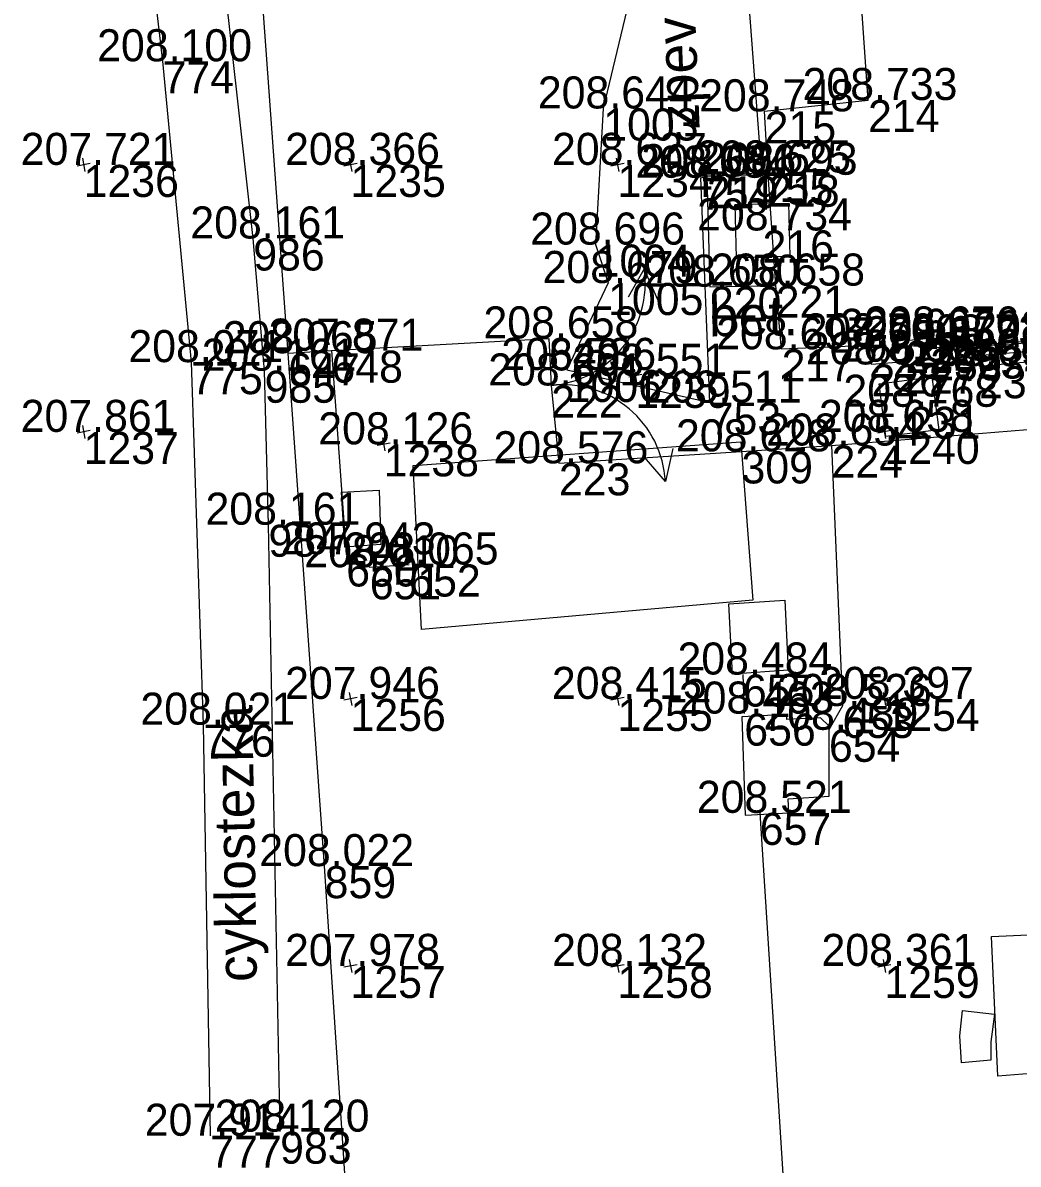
# Model space of a CAD drawing. Extents: x -556590 to -554855, y -1137918 to -1135717.
# Drawn here: x -554982.28 to -554944.99, y -1137757.42 to -1137714.68 of the extents above; entities that cross this region are included whole.
import ezdxf

# ---------------------------------------------------------------- set-up
doc = ezdxf.new("R2010")
doc.units = 0
for name, color, linetype in [('Vrstva 16', 7, 'Continuous'), ('Vrstva 17', 7, 'Continuous'), ('Vrstva 23', 7, 'Continuous'), ('Vrstva 41', 7, 'Continuous'), ('Vrstva 47', 7, 'Continuous'), ('Vrstva 49', 7, 'Continuous'), ('Vrstva 51', 7, 'Continuous'), ('Vrstva 60', 7, 'Continuous'), ('Vrstva 61', 7, 'Continuous')]:
    doc.layers.add(name, color=color, linetype=linetype)

msp = doc.modelspace()

# ---------------------------------------------------------------- linework, layer by layer
at = {"layer": 'Vrstva 16'}
msp.add_lwpolyline([(-554954.353, -1137720.369), (-554956.652, -1137720.423), (-554956.537, -1137724.561), (-554954.072, -1137724.52), (-554954.353, -1137720.369)], dxfattribs=at)
at = {"layer": 'Vrstva 17'}
for p, q in [((-554951.98, -1137730.511), (-554937.843, -1137729.353)), ((-554955.354, -1137730.73), (-554951.98, -1137730.511)), ((-554955.3, -1137739.087), (-554955.249, -1137740.55)), ((-554954.67, -1137744.267), (-554953.509, -1137762.307))]:
    msp.add_line(p, q, dxfattribs=at)
for points in [[(-554953.509, -1137762.307), (-554969.868, -1137763.056), (-554970.971, -1137746.263), (-554972.332, -1137727.052), (-554973.806, -1137706.758), (-554973.974, -1137703.936), (-554973.997, -1137703.261)], [(-554958.483, -1137725.048), (-554959, -1137723.893), (-554959.597, -1137724.958)], [(-554972.332, -1137727.052), (-554970.716, -1137726.957), (-554962.566, -1137726.499)], [(-554962.566, -1137726.499), (-554962.483, -1137728.261), (-554962.192, -1137731.175)], [(-554970.716, -1137726.957), (-554970.161, -1137734.59), (-554969.281, -1137735.07), (-554967.799, -1137734.966)], [(-554957.926, -1137730.62), (-554958.205, -1137731.854), (-554959.001, -1137730.928)], [(-554951.98, -1137730.511), (-554951.571, -1137740.263), (-554952.078, -1137741.156)]]:
    msp.add_lwpolyline(points, dxfattribs=at)
for centre, start, end in [((-554962.795, -1137724.439), 274.6681, 8.188), ((-554962.033, -1137732.069), 3.2176, 96.7375)]:
    msp.add_arc(centre, 3.834, start, end, dxfattribs=at)
at = {"layer": 'Vrstva 23'}
for p, q in [((-554944.283, -1137726.965), (-554946.502, -1137727.152)), ((-554962.192, -1137731.175), (-554955.354, -1137730.73))]:
    msp.add_line(p, q, dxfattribs=at)
for points in [[(-554936.962, -1137725.77), (-554937.612, -1137725.918), (-554942.449, -1137726.25), (-554942.593, -1137726.475), (-554948.283, -1137726.866), (-554948.301, -1137726.503), (-554949.214, -1137726.588), (-554949.216, -1137727.371), (-554950.485, -1137727.473), (-554950.573, -1137726.763), (-554953.849, -1137726.906), (-554954.072, -1137724.52), (-554954.353, -1137720.369), (-554954.486, -1137717.994), (-554950.612, -1137717.57), (-554951.566, -1137703.736)], [(-554946.547, -1137726.803), (-554946.453, -1137727.539), (-554944.242, -1137727.335), (-554944.317, -1137726.654), (-554946.547, -1137726.803)], [(-554955.379, -1137730.366), (-554954.924, -1137736.305), (-554967.337, -1137737.396), (-554967.649, -1137731.255), (-554955.379, -1137730.366)], [(-554968.931, -1137732.178), (-554968.859, -1137734.219), (-554970.215, -1137734.32), (-554970.334, -1137732.256), (-554968.931, -1137732.178)], [(-554953.731, -1137736.305), (-554953.6, -1137738.924), (-554955.689, -1137739.067), (-554955.826, -1137736.435), (-554953.731, -1137736.305)], [(-554955.341, -1137740.666), (-554955.219, -1137744.358), (-554953.583, -1137744.27), (-554953.599, -1137743.744), (-554952.074, -1137743.637), (-554952.064, -1137741.024), (-554952.394, -1137740.711), (-554953.656, -1137740.771), (-554953.662, -1137740.58), (-554955.341, -1137740.666)], [(-554943.227, -1137748.774), (-554942.94, -1137753.906), (-554945.746, -1137754.124), (-554945.984, -1137748.892), (-554943.227, -1137748.774)], [(-554945.871, -1137751.807), (-554946.013, -1137752.846), (-554946.014, -1137753.532), (-554947.106, -1137753.627), (-554947.169, -1137752.618), (-554947.078, -1137751.671), (-554945.871, -1137751.807)]]:
    msp.add_lwpolyline(points, dxfattribs=at)
at = {"layer": 'Vrstva 41'}
msp.add_lwpolyline([(-554950.201, -1137728.194), (-554948.217, -1137727.94), (-554947.963, -1137729.924), (-554949.947, -1137730.178), (-554950.201, -1137728.194)], dxfattribs=at)
at = {"layer": 'Vrstva 47'}
msp.add_lwpolyline([(-554953.538, -1137723.428), (-554955.537, -1137723.483), (-554955.592, -1137721.484), (-554953.593, -1137721.429), (-554953.538, -1137723.428)], dxfattribs=at)
at = {"layer": 'Vrstva 49'}
for p, q in [((-554979.754, -1137719.953), (-554980.246, -1137720.047)), ((-554980.047, -1137719.754), (-554979.953, -1137720.246)), ((-554969.754, -1137719.953), (-554970.246, -1137720.047)), ((-554970.047, -1137719.754), (-554969.953, -1137720.246)), ((-554959.754, -1137719.953), (-554960.246, -1137720.047)), ((-554960.047, -1137719.754), (-554959.953, -1137720.246)), ((-554959.378, -1137727.655), (-554959.284, -1137728.147)), ((-554959.085, -1137727.854), (-554959.577, -1137727.948)), ((-554979.754, -1137729.953), (-554980.246, -1137730.047)), ((-554980.047, -1137729.754), (-554979.953, -1137730.246)), ((-554949.754, -1137729.953), (-554950.246, -1137730.047)), ((-554950.047, -1137729.754), (-554949.953, -1137730.246)), ((-554968.803, -1137730.22), (-554968.709, -1137730.712)), ((-554968.51, -1137730.419), (-554969.002, -1137730.513)), ((-554970.047, -1137739.754), (-554969.953, -1137740.246)), ((-554960.047, -1137739.754), (-554959.953, -1137740.246)), ((-554950.047, -1137739.754), (-554949.953, -1137740.246)), ((-554969.754, -1137739.953), (-554970.246, -1137740.047)), ((-554959.754, -1137739.953), (-554960.246, -1137740.047)), ((-554949.754, -1137739.953), (-554950.246, -1137740.047)), ((-554969.754, -1137749.953), (-554970.246, -1137750.047)), ((-554970.047, -1137749.754), (-554969.953, -1137750.246)), ((-554959.754, -1137749.953), (-554960.246, -1137750.047)), ((-554960.047, -1137749.754), (-554959.953, -1137750.246)), ((-554949.754, -1137749.953), (-554950.246, -1137750.047)), ((-554950.047, -1137749.754), (-554949.953, -1137750.246))]:
    msp.add_line(p, q, dxfattribs=at)
at = {"layer": 'Vrstva 51'}
for points in [[(-554969.785, -1137628.147), (-554967.399, -1137653.447), (-554966.769, -1137664.877), (-554966.888, -1137675.364), (-554967.838, -1137681.325), (-554969.426, -1137687.024), (-554971.39, -1137690.685), (-554975.343, -1137695.897), (-554977.115, -1137698.646), (-554978.514, -1137693.064), (-554980.357, -1137693.689), (-554978.168, -1137701.789), (-554978.169, -1137706.508), (-554977.04, -1137716.12), (-554975.965, -1137727.387), (-554975.515, -1137740.965), (-554975.257, -1137756.361)], [(-554972.638, -1137756.206), (-554973.075, -1137733.475), (-554973.218, -1137727.708), (-554973.644, -1137722.756), (-554975.49, -1137706.199), (-554975.665, -1137703.469), (-554975.108, -1137700.795), (-554973.317, -1137697.546), (-554969.739, -1137692.478), (-554967.391, -1137688.754), (-554966.215, -1137686.165), (-554964.966, -1137680.854), (-554963.935, -1137674.375), (-554963.882, -1137667.989), (-554964.172, -1137662.776), (-554962.839, -1137664.18)], [(-554959.937, -1137681.133), (-554958.62, -1137696.847), (-554958.628, -1137709.906), (-554960.531, -1137717.887), (-554960.817, -1137722.985), (-554960.351, -1137724.423), (-554961.9, -1137727.679)], [(-554961.9, -1137727.679), (-554956.544, -1137728.902), (-554956.873, -1137720.481), (-554956.652, -1137720.423), (-554954.594, -1137720.285), (-554955.148, -1137712.82), (-554952.02, -1137712.38), (-554952.407, -1137709.32), (-554955.389, -1137709.42), (-554955.865, -1137703.797), (-554955.543, -1137697.151), (-554955.755, -1137693.952), (-554956.919, -1137684.337)]]:
    msp.add_lwpolyline(points, dxfattribs=at)
at = {"layer": 'Vrstva 60'}
for p, q in [((-554977.04, -1137716.12), (-554977.04, -1137716.12)), ((-554950.612, -1137717.57), (-554950.612, -1137717.57)), ((-554960.531, -1137717.887), (-554960.531, -1137717.887)), ((-554954.486, -1137717.994), (-554954.486, -1137717.994)), ((-554980, -1137720), (-554980, -1137720)), ((-554970, -1137720), (-554970, -1137720)), ((-554960, -1137720), (-554960, -1137720)), ((-554956.873, -1137720.481), (-554956.873, -1137720.481)), ((-554956.652, -1137720.423), (-554956.652, -1137720.423)), ((-554954.594, -1137720.285), (-554954.594, -1137720.285)), ((-554954.353, -1137720.369), (-554954.353, -1137720.369)), ((-554954.565, -1137722.456), (-554954.565, -1137722.456)), ((-554973.644, -1137722.756), (-554973.644, -1137722.756)), ((-554960.817, -1137722.985), (-554960.817, -1137722.985)), ((-554960.351, -1137724.423), (-554960.351, -1137724.423)), ((-554956.537, -1137724.561), (-554956.537, -1137724.561)), ((-554954.072, -1137724.52), (-554954.072, -1137724.52)), ((-554962.566, -1137726.499), (-554962.566, -1137726.499)), ((-554948.301, -1137726.503), (-554948.301, -1137726.503)), ((-554970.716, -1137726.957), (-554970.716, -1137726.957)), ((-554953.849, -1137726.906), (-554953.849, -1137726.906)), ((-554950.573, -1137726.763), (-554950.573, -1137726.763)), ((-554949.214, -1137726.588), (-554949.214, -1137726.588)), ((-554948.283, -1137726.866), (-554948.283, -1137726.866)), ((-554946.547, -1137726.803), (-554946.547, -1137726.803)), ((-554975.965, -1137727.387), (-554975.965, -1137727.387)), ((-554972.332, -1137727.052), (-554972.332, -1137727.052)), ((-554949.216, -1137727.371), (-554949.216, -1137727.371)), ((-554973.218, -1137727.708), (-554973.218, -1137727.708)), ((-554961.9, -1137727.679), (-554961.9, -1137727.679)), ((-554950.485, -1137727.473), (-554950.485, -1137727.473)), ((-554946.453, -1137727.539), (-554946.453, -1137727.539)), ((-554962.483, -1137728.261), (-554962.483, -1137728.261)), ((-554959.331, -1137727.901), (-554959.331, -1137727.901)), ((-554956.544, -1137728.902), (-554956.544, -1137728.902)), ((-554949.082, -1137729.059), (-554949.082, -1137729.059)), ((-554980, -1137730), (-554980, -1137730)), ((-554950, -1137730), (-554950, -1137730)), ((-554968.756, -1137730.466), (-554968.756, -1137730.466)), ((-554955.354, -1137730.73), (-554955.354, -1137730.73)), ((-554951.98, -1137730.511), (-554951.98, -1137730.511)), ((-554962.192, -1137731.175), (-554962.192, -1137731.175)), ((-554973.075, -1137733.475), (-554973.075, -1137733.475)), ((-554970.161, -1137734.59), (-554970.161, -1137734.59)), ((-554969.281, -1137735.07), (-554969.281, -1137735.07)), ((-554967.799, -1137734.966), (-554967.799, -1137734.966)), ((-554955.3, -1137739.087), (-554955.3, -1137739.087)), ((-554970, -1137740), (-554970, -1137740)), ((-554960, -1137740), (-554960, -1137740)), ((-554950, -1137740), (-554950, -1137740)), ((-554955.249, -1137740.55), (-554955.249, -1137740.55)), ((-554951.571, -1137740.263), (-554951.571, -1137740.263)), ((-554975.515, -1137740.965), (-554975.515, -1137740.965)), ((-554952.078, -1137741.156), (-554952.078, -1137741.156)), ((-554954.67, -1137744.267), (-554954.67, -1137744.267)), ((-554970.971, -1137746.263), (-554970.971, -1137746.263)), ((-554970, -1137750), (-554970, -1137750)), ((-554960, -1137750), (-554960, -1137750)), ((-554950, -1137750), (-554950, -1137750)), ((-554975.257, -1137756.361), (-554975.257, -1137756.361)), ((-554972.638, -1137756.206), (-554972.638, -1137756.206))]:
    msp.add_line(p, q, dxfattribs=at)

# ---------------------------------------------------------------- texts
at = {"layer": 'Vrstva 16'}
msp.add_text('bet.', height=1.5, rotation=0.9529, dxfattribs=at).set_placement((-554956.567, -1137726.43))
at = {"layer": 'Vrstva 51'}
for s, rotation, p in [('zpevn.', 92.2374, (-554956.919, -1137718.672)), ('cyklostezka', 90.96, (-554973.506, -1137750.592))]:
    msp.add_text(s, height=1.5, rotation=rotation, dxfattribs=at).set_placement(p)
at = {"layer": 'Vrstva 60'}
for s, p in [('774', (-554977.04, -1137717.32)), ('214', (-554950.612, -1137718.77)), ('1003', (-554960.531, -1137719.087)), ('215', (-554954.486, -1137719.194)), ('1236', (-554980, -1137721.2)), ('1235', (-554970, -1137721.2)), ('1234', (-554960, -1137721.2)), ('754', (-554956.873, -1137721.681)), ('219', (-554956.652, -1137721.623)), ('755', (-554954.594, -1137721.485)), ('218', (-554954.353, -1137721.569)), ('216', (-554954.565, -1137723.656)), ('986', (-554973.644, -1137723.956)), ('1004', (-554960.817, -1137724.185)), ('1005', (-554960.351, -1137725.623)), ('220', (-554956.537, -1137725.761)), ('221', (-554954.072, -1137725.72)), ('649', (-554962.566, -1137727.699)), ('229', (-554948.301, -1137727.703)), ('648', (-554970.716, -1137728.157)), ('217', (-554953.849, -1137728.106)), ('225', (-554950.573, -1137727.963)), ('228', (-554949.214, -1137727.788)), ('230', (-554948.283, -1137728.066)), ('234', (-554946.547, -1137728.003)), ('775', (-554975.965, -1137728.587)), ('647', (-554972.332, -1137728.252)), ('227', (-554949.216, -1137728.571)), ('985', (-554973.218, -1137728.908)), ('1006', (-554961.9, -1137728.879)), ('226', (-554950.485, -1137728.673)), ('235', (-554946.453, -1137728.739)), ('222', (-554962.483, -1137729.461)), ('1239', (-554959.331, -1137729.101)), ('753', (-554956.544, -1137730.102)), ('231', (-554949.082, -1137730.259)), ('1237', (-554980, -1137731.2)), ('1240', (-554950, -1137731.2)), ('1238', (-554968.756, -1137731.666)), ('309', (-554955.354, -1137731.93)), ('224', (-554951.98, -1137731.711)), ('223', (-554962.192, -1137732.375)), ('984', (-554973.075, -1137734.675)), ('650', (-554970.161, -1137735.79)), ('651', (-554969.281, -1137736.27)), ('652', (-554967.799, -1137736.166)), ('655', (-554955.3, -1137740.287)), ('1256', (-554970, -1137741.2)), ('1255', (-554960, -1137741.2)), ('653', (-554951.571, -1137741.463)), ('1254', (-554950, -1137741.2)), ('656', (-554955.249, -1137741.75)), ('776', (-554975.515, -1137742.165)), ('654', (-554952.078, -1137742.356)), ('657', (-554954.67, -1137745.467)), ('859', (-554970.971, -1137747.463)), ('1257', (-554970, -1137751.2)), ('1258', (-554960, -1137751.2)), ('1259', (-554950, -1137751.2)), ('777', (-554975.257, -1137757.561)), ('983', (-554972.638, -1137757.406))]:
    msp.add_text(s, height=1.2, dxfattribs=at).set_placement(p)
at = {"layer": 'Vrstva 61'}
for s, p in [('208.100', (-554979.491, -1137716.12)), ('208.644', (-554962.982, -1137717.887)), ('208.733', (-554953.064, -1137717.57)), ('208.748', (-554956.94, -1137717.994)), ('207.721', (-554982.357, -1137720)), ('208.366', (-554972.452, -1137720)), ('208.627', (-554962.452, -1137720)), ('208.684', (-554959.324, -1137720.481)), ('208.696', (-554959.104, -1137720.423)), ('208.625', (-554957.05, -1137720.285)), ('208.693', (-554956.805, -1137720.369)), ('208.734', (-554957.016, -1137722.456)), ('208.161', (-554976.001, -1137722.756)), ('208.696', (-554963.269, -1137722.985)), ('208.679', (-554962.805, -1137724.423)), ('208.650', (-554958.988, -1137724.561)), ('208.658', (-554956.526, -1137724.52)), ('208.658', (-554965.02, -1137726.499)), ('208.697', (-554956.301, -1137726.906)), ('208.704', (-554953.024, -1137726.763)), ('208.697', (-554951.666, -1137726.588)), ('208.676', (-554950.753, -1137726.503)), ('208.659', (-554950.737, -1137726.866)), ('208.737', (-554948.999, -1137726.803)), ('208.921', (-554946.674, -1137726.654)), ('208.065', (-554974.788, -1137727.052)), ('207.871', (-554973.073, -1137726.957)), ('208.809', (-554946.696, -1137727.335)), ('208.071', (-554978.322, -1137727.387)), ('208.161', (-554975.575, -1137727.708)), ('208.536', (-554964.352, -1137727.679)), ('208.678', (-554952.939, -1137727.473)), ('208.688', (-554951.67, -1137727.371)), ('208.696', (-554948.905, -1137727.539)), ('208.551', (-554961.688, -1137727.901)), ('208.601', (-554964.84, -1137728.261)), ('208.511', (-554958.901, -1137728.902)), ('208.768', (-554951.536, -1137729.059)), ('207.861', (-554982.357, -1137730)), ('208.658', (-554952.454, -1137730)), ('208.126', (-554971.208, -1137730.466)), ('208.628', (-554957.808, -1137730.73)), ('208.654', (-554954.431, -1137730.511)), ('208.576', (-554964.644, -1137731.175)), ('208.161', (-554975.432, -1137733.475)), ('207.943', (-554972.613, -1137734.59)), ('208.065', (-554970.255, -1137734.966)), ('208.010', (-554971.732, -1137735.07)), ('208.484', (-554957.751, -1137739.087)), ('207.946', (-554972.452, -1137740)), ('208.415', (-554962.456, -1137740)), ('208.397', (-554952.452, -1137740)), ('208.463', (-554957.701, -1137740.55)), ('208.526', (-554954.023, -1137740.263)), ('208.021', (-554977.872, -1137740.965)), ('208.489', (-554954.532, -1137741.156)), ('208.521', (-554957.027, -1137744.267)), ('208.022', (-554973.419, -1137746.263)), ('207.978', (-554972.454, -1137750)), ('208.132', (-554962.448, -1137750)), ('208.361', (-554952.357, -1137750)), ('207.914', (-554977.708, -1137756.361)), ('208.120', (-554975.089, -1137756.206))]:
    msp.add_text(s, height=1.2, dxfattribs=at).set_placement(p)

doc.saveas('drawing.dxf')
